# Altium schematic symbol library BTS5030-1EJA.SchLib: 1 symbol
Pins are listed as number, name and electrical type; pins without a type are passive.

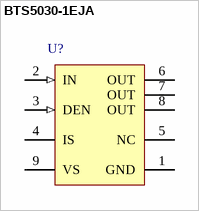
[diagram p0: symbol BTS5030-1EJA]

## BTS5030-1EJA
designator U?
PROFET+ 12 V Smart High-Side Power Switch, 1 Channel, 30 mOhm, 6 A Load Current, -40 to 150 degC, PG-DSO-8-27, Reel, Green; Manufacturer: Infineon; PartNumber: BTS5030-1EJA; Channels: 1; Green: TRUE; Group: Automotive Qualified; Load Current (typ): 6 A; Packing: Tube; Ptot (max): 1.7 W; Recommended Operating Voltage Max.: 28 V; Recommended Operating Voltage Min.: 5 V; RON @ 25degreesC: 30 mOhm; RON(max) @ 150degreesC: 60 mOhm; toff (max): 230 us
footprint INF-PG-DSO-8-27_N (SOP, 8-Leads, Body 4.9x3.9mm, Pitch 1.27mm, Thermal Pad 3.2x2.85mm, IPC Medium Density)
footprint INF-PG-DSO-8-27_L (SOP, 8-Leads, Body 4.9x3.9mm, Pitch 1.27mm, Thermal Pad 3.2x2.85mm, IPC High Density)
footprint INF-PG-DSO-8-27_M (SOP, 8-Leads, Body 4.9x3.9mm, Pitch 1.27mm, Thermal Pad 3.2x2.85mm, IPC Low Density)
pins: 1 GND (power) "GrouND; Ground connection", 2 IN (in) "INput channel; Input signal for channel activation", 3 DEN (in) "Diagnostic ENable; Digital signal to enable/disable the diagnosis of the device", 4 IS (hiz) "Sense; Sense current of the selected channel", 5 NC "Not Connected; No internal connection to the chip", 6 OUT (power) "OUTput; Protected high side power output channel", 7 OUT (power) "OUTput; Protected high side power output channel", 8 OUT (power) "OUTput; Protected high side power output channel", 9 VS (power) "Voltage Supply; Battery voltage"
